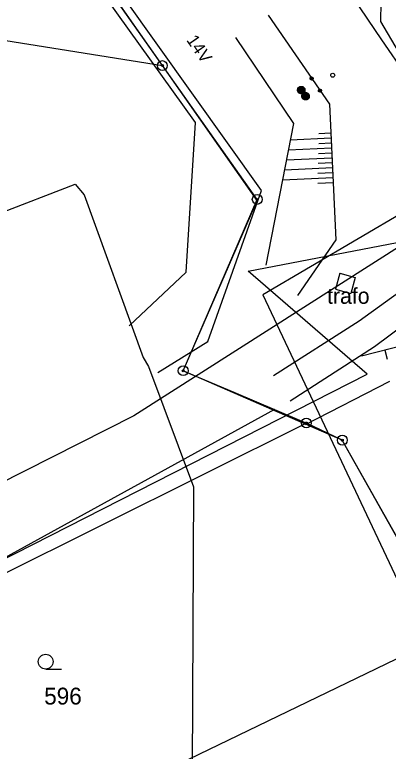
# Model space of a CAD drawing. Extents: x -469926 to -462499, y -1098642 to -1092733.
# Drawn here: x -465914.7 to -465877.1, y -1094440.6 to -1094366.3 of the extents above; entities that cross this region are included whole.
import ezdxf

# ---------------------------------------------------------------- set-up
doc = ezdxf.new("R2010")
doc.units = 0
for name, color, linetype in [('Vrstva 1', 7, 'Continuous'), ('Vrstva 10', 7, 'Continuous'), ('Vrstva 11', 7, 'Continuous'), ('Vrstva 12', 7, 'Continuous'), ('Vrstva 13', 7, 'Continuous'), ('Vrstva 14', 7, 'Continuous'), ('Vrstva 24', 7, 'Continuous'), ('Vrstva 25', 7, 'Continuous'), ('Vrstva 26', 7, 'Continuous'), ('Vrstva 30', 7, 'Continuous'), ('Vrstva 4', 7, 'Continuous'), ('Vrstva 48', 7, 'Continuous'), ('Vrstva 50', 7, 'Continuous'), ('Vrstva 62', 7, 'Continuous'), ('Vrstva 63', 7, 'Continuous'), ('Vrstva 8', 7, 'Continuous')]:
    doc.layers.add(name, color=color, linetype=linetype)

# ---------------------------------------------------------------- blocks, each defined once
blk = doc.blocks.new('2T')
at = {"layer": 'Vrstva 63'}
for points in [[(-0.748, 0.968), (0.02, 1.491), (0.148, 1.469), (-0.767, 0.906)], [(-0.727, 1.041), (-0.049, 1.496), (0.02, 1.491), (-0.748, 0.968)], [(-0.707, 1.078), (-0.187, 1.48), (-0.049, 1.496), (-0.727, 1.041)], [(-0.779, 0.818), (0.247, 1.437), (0.322, 1.403), (-0.784, 0.724)], [(-0.784, 0.724), (0.322, 1.403), (0.405, 1.352), (-0.78, 0.646)], [(-0.78, 0.646), (0.405, 1.352), (0.485, 1.287), (-0.759, 0.557)], [(-0.767, 0.906), (0.148, 1.469), (0.247, 1.437), (-0.779, 0.818)], [(-0.759, 0.557), (0.485, 1.287), (0.55, 1.208), (-0.725, 0.445)], [(-0.725, 0.445), (0.55, 1.208), (0.628, 1.088), (-0.676, 0.361)], [(-0.664, 1.15), (-0.26, 1.461), (-0.187, 1.48), (-0.707, 1.078)], [(-0.676, 0.361), (0.628, 1.088), (0.675, 0.971), (-0.604, 0.259)], [(-0.616, 1.219), (-0.352, 1.422), (-0.26, 1.461), (-0.664, 1.15)], [(-0.563, 1.28), (-0.45, 1.371), (-0.352, 1.422), (-0.616, 1.219)], [(-0.604, 0.259), (0.675, 0.971), (0.705, 0.859), (-0.525, 0.183)], [(-0.525, 0.183), (0.705, 0.859), (0.711, 0.705), (-0.442, 0.118)], [(-0.442, 0.118), (0.711, 0.705), (0.692, 0.572), (-0.354, 0.068)], [(-0.354, 0.068), (0.692, 0.572), (0.661, 0.472), (-0.243, 0.029)], [(-0.243, 0.029), (0.661, 0.472), (0.614, 0.377), (-0.151, 0.007)], [(-0.151, 0.007), (0.614, 0.377), (0.555, 0.289), (-0.086, 0)], [(-0.086, 0), (0.555, 0.289), (0.499, 0.223), (0, 0)], [(0, 0), (0.499, 0.223), (0.411, 0.15), (0.1, 0.008)], [(0.1, 0.008), (0.411, 0.15), (0.347, 0.103), (0.213, 0.045)], [(0.213, 0.045), (0.347, 0.103), (0.258, 0.055), (0.256, 0.054)], [(-0.779, -0.682), (0.247, -0.063), (0.322, -0.097), (-0.784, -0.776)], [(-0.784, -0.776), (0.322, -0.097), (0.405, -0.148), (-0.78, -0.854)], [(-0.78, -0.854), (0.405, -0.148), (0.485, -0.213), (-0.759, -0.943)], [(-0.767, -0.594), (0.148, -0.031), (0.247, -0.063), (-0.779, -0.682)], [(-0.748, -0.532), (0.02, -0.009), (0.148, -0.031), (-0.767, -0.594)], [(-0.759, -0.943), (0.485, -0.213), (0.55, -0.292), (-0.725, -1.055)], [(-0.727, -0.459), (-0.049, -0.004), (0.02, -0.009), (-0.748, -0.532)], [(-0.707, -0.422), (-0.187, -0.02), (-0.049, -0.004), (-0.727, -0.459)], [(-0.725, -1.055), (0.55, -0.292), (0.628, -0.412), (-0.676, -1.139)], [(-0.664, -0.35), (-0.26, -0.039), (-0.187, -0.02), (-0.707, -0.422)], [(-0.676, -1.139), (0.628, -0.412), (0.675, -0.529), (-0.604, -1.241)], [(-0.616, -0.281), (-0.352, -0.078), (-0.26, -0.039), (-0.664, -0.35)], [(-0.563, -0.22), (-0.45, -0.129), (-0.352, -0.078), (-0.616, -0.281)], [(-0.604, -1.241), (0.675, -0.529), (0.705, -0.641), (-0.525, -1.317)], [(-0.525, -1.317), (0.705, -0.641), (0.711, -0.795), (-0.442, -1.382)], [(-0.442, -1.382), (0.711, -0.795), (0.692, -0.928), (-0.354, -1.432)], [(-0.354, -1.432), (0.692, -0.928), (0.661, -1.028), (-0.243, -1.471)], [(-0.243, -1.471), (0.661, -1.028), (0.614, -1.123), (-0.151, -1.493)], [(-0.151, -1.493), (0.614, -1.123), (0.555, -1.211), (-0.086, -1.5)], [(-0.086, -1.5), (0.555, -1.211), (0.499, -1.277), (0, -1.5)], [(0, -1.5), (0.499, -1.277), (0.411, -1.35), (0.1, -1.492)], [(0.1, -1.492), (0.411, -1.35), (0.347, -1.397), (0.213, -1.455)], [(0.213, -1.455), (0.347, -1.397), (0.258, -1.445), (0.256, -1.446)]]:
    blk.add_lwpolyline(points, close=True, dxfattribs=at)
for centre in [(-0.037, 0.747), (-0.037, -0.753)]:
    blk.add_circle(centre, 0.75, dxfattribs=at)
blk = doc.blocks.new('TECKA')
at = {"layer": 'Vrstva 63'}
for p, q in [((-0.314, 0.01), (0.17, 0.264)), ((-0.314, -0.004), (0.183, 0.256)), ((-0.314, -0.018), (0.194, 0.247)), ((-0.313, 0.024), (0.158, 0.271)), ((-0.313, -0.031), (0.204, 0.239)), ((-0.311, 0.04), (0.145, 0.278)), ((-0.31, 0.055), (0.131, 0.286)), ((-0.31, -0.045), (0.213, 0.231)), ((-0.308, -0.058), (0.223, 0.221)), ((-0.306, 0.07), (0.116, 0.291)), ((-0.306, -0.07), (0.233, 0.211)), ((-0.302, 0.087), (0.1, 0.298)), ((-0.302, -0.083), (0.241, 0.202)), ((-0.299, -0.095), (0.248, 0.192)), ((-0.297, 0.104), (0.083, 0.303)), ((-0.295, -0.107), (0.256, 0.182)), ((-0.291, -0.119), (0.263, 0.171)), ((-0.29, 0.122), (0.065, 0.308)), ((-0.286, -0.131), (0.27, 0.161)), ((-0.281, 0.14), (0.045, 0.311)), ((-0.28, -0.142), (0.276, 0.149)), ((-0.274, -0.152), (0.282, 0.139)), ((-0.271, 0.16), (0.022, 0.313)), ((-0.268, -0.164), (0.287, 0.127)), ((-0.262, -0.174), (0.292, 0.116)), ((-0.257, 0.182), (-0.004, 0.314)), ((-0.255, -0.185), (0.297, 0.104)), ((-0.246, -0.195), (0.3, 0.092)), ((-0.239, -0.204), (0.304, 0.08)), ((-0.238, 0.205), (-0.034, 0.312)), ((-0.23, -0.214), (0.307, 0.067)), ((-0.221, -0.223), (0.309, 0.054)), ((-0.211, -0.233), (0.311, 0.041)), ((-0.209, 0.234), (-0.073, 0.306)), ((-0.201, -0.241), (0.313, 0.028)), ((-0.19, -0.25), (0.313, 0.014)), ((-0.179, -0.258), (0.314, 0)), ((-0.167, -0.266), (0.314, -0.014)), ((-0.155, -0.273), (0.313, -0.029)), ((-0.141, -0.281), (0.311, -0.044)), ((-0.127, -0.287), (0.308, -0.059)), ((-0.112, -0.293), (0.306, -0.075)), ((-0.096, -0.299), (0.301, -0.091)), ((-0.078, -0.305), (0.295, -0.109)), ((-0.06, -0.308), (0.287, -0.127)), ((-0.039, -0.312), (0.278, -0.145)), ((-0.016, -0.314), (0.267, -0.165)), ((0.011, -0.314), (0.253, -0.187)), ((0.042, -0.311), (0.231, -0.212)), ((0.088, -0.301), (0.198, -0.244))]:
    blk.add_line(p, q, dxfattribs=at)
blk.add_circle((0, 0), 0.314, dxfattribs=at)

msp = doc.modelspace()

# ---------------------------------------------------------------- linework, layer by layer
at = {"layer": 'Vrstva 1'}
for p, q in [((-465899.84, -1094371.44), (-465915.04, -1094349.79)), ((-466020.96, -1094351.95), (-465899.84, -1094371.44)), ((-465890.27, -1094384.94), (-465899.84, -1094371.44)), ((-465897.74, -1094402.23), (-465890.27, -1094384.94)), ((-465897.74, -1094402.23), (-465892.4, -1094404.51)), ((-465892.4, -1094404.51), (-465888.54, -1094406.15)), ((-465888.54, -1094406.15), (-465885.32, -1094407.51)), ((-465885.32, -1094407.51), (-465943.45, -1094436.5)), ((-465881.69, -1094409.24), (-465885.32, -1094407.51)), ((-465870.77, -1094428.67), (-465881.69, -1094409.24)), ((-465870.77, -1094428.67), (-465922.1, -1094453.49))]:
    msp.add_line(p, q, dxfattribs=at)
at = {"layer": 'Vrstva 10'}
msp.add_lwpolyline([(-465809.93, -1094647.11), (-465809.53, -1094606.14), (-465811.35, -1094565.9), (-465798.73, -1094567.35), (-465791.33, -1094568.21), (-465808.97, -1094527.39), (-465826.29, -1094474.97), (-465841.49, -1094454.46), (-465856.3, -1094454.39), (-465881.69, -1094409.24), (-465897.74, -1094402.23), (-465890.27, -1094385.04), (-465899.84, -1094371.44), (-465920.21, -1094342.38), (-465937.77, -1094317.53), (-465976.87, -1094259.1), (-466033.38, -1094177.84)], dxfattribs=at)
at = {"layer": 'Vrstva 12'}
for p, q in [((-465949.55, -1094399.08), (-465908.62, -1094383.42)), ((-465908.62, -1094383.42), (-465907.73, -1094384.49)), ((-465907.73, -1094384.49), (-465901.78, -1094400.9)), ((-465901.78, -1094400.9), (-465901.25, -1094401.79)), ((-465901.25, -1094401.79), (-465896.7, -1094413.95)), ((-465885.419, -1094407.67), (-465876.909, -1094403.289)), ((-465896.7, -1094413.95), (-465896.94, -1094470.2))]:
    msp.add_line(p, q, dxfattribs=at)
at = {"layer": 'Vrstva 13'}
for p, q in [((-465872.466, -1094391.789), (-465879.993, -1094397.235)), ((-465871.656, -1094394.748), (-465878.432, -1094399.812)), ((-465879.993, -1094397.235), (-465888.627, -1094402.743)), ((-465878.432, -1094399.812), (-465886.954, -1094405.319))]:
    msp.add_line(p, q, dxfattribs=at)
at = {"layer": 'Vrstva 14'}
for p, q in [((-465856.392, -1094374.932), (-465889.696, -1094394.582)), ((-465891.198, -1094392.196), (-465846.188, -1094383.458)), ((-465879.174, -1094402.564), (-465891.198, -1094392.196)), ((-465889.696, -1094394.582), (-465839.936, -1094500.298)), ((-465979.095, -1094453.469), (-465879.174, -1094402.564))]:
    msp.add_line(p, q, dxfattribs=at)
at = {"layer": 'Vrstva 24'}
for centre, radius in [((-465899.84, -1094371.44), 0.5), ((-465899.84, -1094371.44), 0.1), ((-465890.27, -1094384.94), 0.5), ((-465890.27, -1094384.94), 0.1), ((-465897.74, -1094402.23), 0.5), ((-465897.74, -1094402.23), 0.1), ((-465885.32, -1094407.51), 0.5), ((-465885.32, -1094407.51), 0.1), ((-465881.69, -1094409.24), 0.5), ((-465881.69, -1094409.24), 0.1)]:
    msp.add_circle(centre, radius, dxfattribs=at)
at = {"layer": 'Vrstva 25'}
msp.add_line((-465911.61, -1094432.34), (-465910.01, -1094432.34), dxfattribs=at)
msp.add_circle((-465911.61, -1094431.59), 0.75, dxfattribs=at)
at = {"layer": 'Vrstva 26'}
for p, q in [((-465881.942, -1094392.39), (-465882.389, -1094393.986)), ((-465881.942, -1094392.39), (-465880.39, -1094392.831)), ((-465880.39, -1094392.831), (-465880.837, -1094394.427)), ((-465882.389, -1094393.986), (-465880.837, -1094394.427))]:
    msp.add_line(p, q, dxfattribs=at)
at = {"layer": 'Vrstva 4'}
for p, q in [((-465889.856, -1094384.039), (-465914.185, -1094349.841)), ((-465896.514, -1094377.194), (-465909.939, -1094358.367)), ((-465897.454, -1094392.302), (-465896.514, -1094377.194)), ((-465895.251, -1094399.269), (-465889.856, -1094384.039)), ((-465903.19, -1094397.698), (-465897.454, -1094392.302)), ((-465900.313, -1094402.399), (-465895.251, -1094399.269)), ((-465888.54, -1094406.15), (-465947.05, -1094438.3))]:
    msp.add_line(p, q, dxfattribs=at)
at = {"layer": 'Vrstva 48'}
for p, q in [((-465882.837, -1094378.768), (-465886.914, -1094378.961)), ((-465882.837, -1094378.768), (-465886.914, -1094378.961)), ((-465882.861, -1094378.268), (-465884.048, -1094378.325)), ((-465882.861, -1094378.268), (-465884.048, -1094378.325)), ((-465882.814, -1094379.268), (-465884.073, -1094379.327)), ((-465882.814, -1094379.268), (-465884.073, -1094379.327)), ((-465882.79, -1094379.767), (-465887.111, -1094379.971)), ((-465882.79, -1094379.767), (-465887.111, -1094379.971)), ((-465882.766, -1094380.266), (-465884.099, -1094380.33)), ((-465882.766, -1094380.266), (-465884.099, -1094380.33)), ((-465882.743, -1094380.766), (-465887.307, -1094380.982)), ((-465882.743, -1094380.766), (-465887.307, -1094380.982)), ((-465882.696, -1094381.765), (-465887.503, -1094381.992)), ((-465882.696, -1094381.765), (-465887.503, -1094381.992)), ((-465882.719, -1094381.265), (-465884.125, -1094381.332)), ((-465882.719, -1094381.265), (-465884.125, -1094381.332)), ((-465882.672, -1094382.265), (-465884.151, -1094382.334)), ((-465882.672, -1094382.265), (-465884.151, -1094382.334)), ((-465882.648, -1094382.763), (-465887.699, -1094383.002)), ((-465882.648, -1094382.763), (-465887.699, -1094383.002)), ((-465882.625, -1094383.263), (-465884.176, -1094383.336)), ((-465882.625, -1094383.263), (-465884.176, -1094383.336))]:
    msp.add_line(p, q, dxfattribs=at)
at = {"layer": 'Vrstva 62'}
for p, q in [((-465882.439, -1094361.831), (-465877.75, -1094368.84)), ((-465877.821, -1094365.034), (-465877.836, -1094366.991)), ((-465889.166, -1094366.335), (-465883, -1094375.33)), ((-465877.836, -1094366.991), (-465876.053, -1094370.01)), ((-465886.59, -1094377.29), (-465892.434, -1094368.596)), ((-465877.75, -1094368.84), (-465871.55, -1094377.885)), ((-465883, -1094375.33), (-465882.352, -1094389.025)), ((-465889.361, -1094391.565), (-465886.59, -1094377.29)), ((-465882.352, -1094389.025), (-465886.22, -1094394.63)), ((-465874.92, -1094399.53), (-465879.77, -1094400.75)), ((-465877.407, -1094400.155), (-465877.177, -1094401.067))]:
    msp.add_line(p, q, dxfattribs=at)
at = {"layer": 'Vrstva 8'}
for p, q in [((-465855.516, -1094376.677), (-465902.727, -1094406.775)), ((-465902.727, -1094406.775), (-465988.347, -1094450.117))]:
    msp.add_line(p, q, dxfattribs=at)
msp.add_circle((-465882.661, -1094372.405), 0.2, dxfattribs=at)

# ---------------------------------------------------------------- block references
at = {"layer": 'Vrstva 11', "xscale": 0.49999999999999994, "yscale": 0.5000000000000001}
for name, p, rotation in [('TECKA', (-465884.787, -1094372.736), 34.64121758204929), ('2T', (-465885.603, -1094374.204), 34.64121758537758), ('TECKA', (-465883.942, -1094373.958), 34.64121758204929)]:
    msp.add_blockref(name, p, dxfattribs=dict(at, rotation=rotation))

# ---------------------------------------------------------------- texts
at = {"layer": 'Vrstva 11'}
msp.add_text('14V', height=1.25, rotation=304.64122, dxfattribs=at).set_placement((-465897.467, -1094368.865))
at = {"layer": 'Vrstva 30'}
msp.add_text('trafo', height=1.6, dxfattribs=at).set_placement((-465883.228, -1094395.478))
at = {"layer": 'Vrstva 50'}
msp.add_text('596', height=1.7, dxfattribs=at).set_placement((-465911.762, -1094435.92))

doc.saveas('drawing.dxf')
